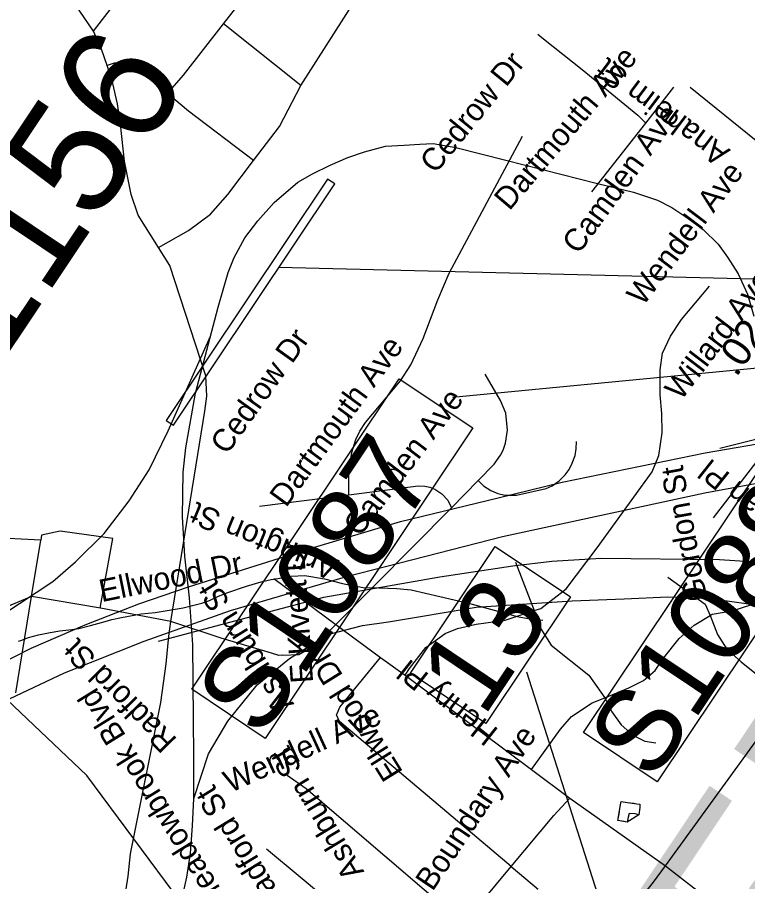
# Model space of a CAD drawing. Extents: x 1716282 to 1717158, y 799307 to 801078.
# Drawn here: x 1716763 to 1716807.8, y 800806.9 to 800859.9 of the extents above; entities that cross this region are included whole.
import ezdxf

# ---------------------------------------------------------------- set-up
doc = ezdxf.new("R2010")
doc.units = 0
for name, color, linetype in [('Exist Hydrographic Misc Water Feature', 7, 'Continuous'), ('Exist Road Non-System Structure Non-Sys Other Number Label', 7, 'Continuous'), ('Exist Road Non-System Type 51', 7, 'Continuous'), ('Exist Road Non-System Type 51 Label', 7, 'Continuous'), ('Exist Road Primary US Structure Ovrhead Sign CELL', 7, 'Continuous'), ('Exist Road Primary US Structure Standard Bridge Number Label', 7, 'Continuous'), ('Exist Road Secondary Mileage Hundredths English Label', 7, 'Continuous'), ('Exist Road Secondary Structure Standard Bridge Number Label', 7, 'Continuous'), ('Exist Road Secondary Type 51 Attributed', 7, 'Continuous'), ('Exist Road Secondary Type 51 Label', 7, 'Continuous'), ('Old_Level_1', 7, 'Continuous'), ('Prop Road Primary US Projected', 7, 'Continuous'), ('Prop Road Secondary Projected', 7, 'Continuous')]:
    doc.layers.add(name, color=color, linetype=linetype)

msp = doc.modelspace()

# ---------------------------------------------------------------- linework, layer by layer
at = {"layer": 'Exist Hydrographic Misc Water Feature'}
for points in [[(1716763.096, 800821.605), (1716763.227, 800821.662), (1716763.697, 800821.833), (1716764.31, 800822.011), (1716765.036, 800822.149), (1716765.624, 800822.237), (1716766.358, 800822.336), (1716766.784, 800822.394), (1716767.502, 800822.57), (1716768.415, 800822.825), (1716768.81, 800822.943), (1716769.416, 800823.057), (1716770.624, 800823.284), (1716771.487, 800823.363), (1716773.203, 800823.665), (1716774.341, 800823.942), (1716774.81, 800824.113), (1716775.327, 800824.357), (1716775.868, 800824.584), (1716777.088, 800824.98), (1716777.976, 800825.252), (1716778.597, 800825.391), (1716779, 800825.466), (1716779.831, 800825.601), (1716780.66, 800825.632), (1716781.865, 800825.441), (1716782.964, 800825.148), (1716784.24, 800824.909), (1716785.204, 800824.881), (1716786.3, 800824.838), (1716787.191, 800824.753), (1716790.706, 800823.934), (1716792.728, 800823.396), (1716793.699, 800823.12), (1716794.132, 800823.034), (1716794.518, 800822.982), (1716795.264, 800822.893)], [(1716779.752, 800768.606), (1716779.969, 800768.981), (1716779.06, 800773.412), (1716773.302, 800782.926), (1716773.169, 800783.886), (1716773.397, 800784.735), (1716773.329, 800786.33), (1716773.47, 800786.879), (1716774.435, 800788.237), (1716774.859, 800788.785), (1716775.418, 800789.507), (1716776.092, 800791.022), (1716776.356, 800794.292), (1716775.692, 800799.57), (1716773.061, 800805.606), (1716767.28, 800813.366), (1716762.4, 800818.012), (1716761.079, 800818.592)], [(1716800.07, 800811.775), (1716800.457, 800811.724), (1716800.842, 800811.67), (1716801.035, 800811.644), (1716801.228, 800811.618), (1716801.225, 800811.408), (1716801.164, 800810.959), (1716800.923, 800811.016), (1716800.562, 800811.054), (1716800.503, 800810.814), (1716800.435, 800810.508), (1716800.258, 800810.558), (1716799.873, 800810.612), (1716799.943, 800811.022), (1716800.004, 800811.471), (1716800.07, 800811.775)], [(1716800.07, 800811.775), (1716800.457, 800811.724), (1716801.035, 800811.644), (1716801.228, 800811.618), (1716801.225, 800811.408), (1716801.164, 800810.959), (1716800.435, 800810.508), (1716799.873, 800810.612), (1716800.004, 800811.471), (1716800.07, 800811.775)]]:
    msp.add_lwpolyline(points, dxfattribs=at)
at = {"layer": 'Exist Road Non-System Type 51'}
for p, q in [((1716767.686, 800859.012), (1716775.828, 800869.582)), ((1716775.679, 800859.473), (1716780.784, 800866.012)), ((1716780.415, 800855.698), (1716775.679, 800859.473)), ((1716801.589, 800853.374), (1716803.301, 800855.585)), ((1716798.269, 800849.175), (1716801.589, 800853.374)), ((1716805.745, 800829.179), (1716808.41, 800832.66)), ((1716789.67, 800829.785), (1716791.308, 800831.467)), ((1716777.878, 800829.887), (1716783.361, 800830.59)), ((1716782.569, 800822.64), (1716789.67, 800829.785)), ((1716763.89, 800824.349), (1716764.458, 800827.805)), ((1716793.597, 800826.457), (1716794.742, 800823.488)), ((1716778.766, 800825.447), (1716782.569, 800822.64)), ((1716762.934, 800818.435), (1716763.89, 800824.349)), ((1716768.126, 800823.638), (1716763.89, 800824.349)), ((1716772.447, 800822.815), (1716768.126, 800823.638)), ((1716782.569, 800822.64), (1716785.313, 800820.621)), ((1716785.313, 800820.621), (1716786.809, 800819.519)), ((1716786.809, 800819.519), (1716794.579, 800813.741)), ((1716802.788, 800807.834), (1716810.25, 800818.107)), ((1716794.579, 800813.741), (1716796.929, 800811.985)), ((1716796.929, 800811.985), (1716802.788, 800807.834)), ((1716790.405, 800804.316), (1716793.33, 800807.804)), ((1716793.33, 800807.804), (1716799.024, 800803.003)), ((1716802.788, 800807.834), (1716806.624, 800804.887))]:
    msp.add_line(p, q, dxfattribs=at)
for points in [[(1716780.415, 800855.698), (1716784.463, 800862.046), (1716784.606, 800862.629), (1716784.528, 800862.924), (1716784.476, 800863.148), (1716784.147, 800863.573), (1716780.784, 800866.012)], [(1716767.686, 800859.012), (1716766.863, 800860.237), (1716765.985, 800861.662), (1716765.21, 800862.818), (1716764.686, 800863.727)], [(1716772.238, 800855.2), (1716773.216, 800856.327), (1716775.679, 800859.473)], [(1716768.537, 800856.922), (1716768.174, 800857.907), (1716767.686, 800859.012)], [(1716794.956, 800858.838), (1716795.3, 800858.554), (1716797.685, 800856.67), (1716801.102, 800853.878), (1716801.589, 800853.374)], [(1716772.238, 800855.2), (1716771.5, 800855.803), (1716770.605, 800856.642), (1716770.173, 800856.918), (1716769.784, 800857.047), (1716769.377, 800857.097), (1716768.967, 800857.059), (1716768.537, 800856.922)], [(1716771.689, 800845.752), (1716770.443, 800847.742), (1716770.001, 800848.998), (1716769.598, 800851.045), (1716769.355, 800853.323), (1716769.159, 800854.569), (1716768.872, 800855.808), (1716768.537, 800856.922)], [(1716777.517, 800851.086), (1716779.109, 800853.179), (1716780.415, 800855.698)], [(1716804.298, 800855.582), (1716808.47, 800852.236), (1716816.668, 800845.833), (1716820.932, 800842.974)], [(1716777.517, 800851.086), (1716773.532, 800854.109), (1716772.238, 800855.2)], [(1716783.361, 800830.59), (1716783.368, 800832.016), (1716783.553, 800833.188), (1716783.784, 800833.985), (1716784.036, 800834.498), (1716784.386, 800835.021), (1716786.538, 800837.587), (1716787.169, 800838.556), (1716787.931, 800840.181), (1716788.816, 800842.538), (1716789.517, 800844.18), (1716794.023, 800852.575)], [(1716771.689, 800845.752), (1716773.523, 800846.789), (1716774.875, 800847.803), (1716775.944, 800849.01), (1716777.517, 800851.086)], [(1716772.447, 800822.815), (1716774.515, 800835.724), (1716774.641, 800836.638), (1716774.58, 800837.894), (1716772.375, 800844.644), (1716771.689, 800845.752)], [(1716794.742, 800823.488), (1716795.144, 800823.624), (1716796.706, 800824.829), (1716798.6, 800827.343), (1716801.966, 800831.991), (1716802.379, 800832.989), (1716802.591, 800834.381), (1716802.575, 800835.568), (1716802.475, 800836.711), (1716802.47, 800838.245), (1716802.603, 800839.277), (1716803.103, 800840.325), (1716803.786, 800841.347), (1716805.499, 800843.385)], [(1716791.308, 800831.467), (1716792.286, 800832.462), (1716792.677, 800833.02), (1716792.833, 800833.328), (1716792.981, 800833.761), (1716793.095, 800834.548), (1716792.994, 800835.602), (1716792.664, 800836.368), (1716791.727, 800837.979)], [(1716791.308, 800831.467), (1716791.633, 800831.146), (1716792.082, 800830.845), (1716792.497, 800830.671), (1716792.936, 800830.576), (1716793.655, 800830.575), (1716795.471, 800830.967), (1716795.843, 800831.147), (1716796.264, 800831.448), (1716796.636, 800831.812), (1716796.88, 800832.148), (1716797.072, 800832.519), (1716797.242, 800833.005), (1716797.312, 800833.412), (1716797.325, 800833.848)], [(1716783.361, 800830.59), (1716787.612, 800831.139), (1716788.026, 800831.128), (1716788.339, 800831.06), (1716788.636, 800830.944), (1716789.078, 800830.653), (1716789.43, 800830.262), (1716789.67, 800829.785)], [(1716805.53, 800823.194), (1716805.651, 800823.27), (1716806.881, 800823.467), (1716808.088, 800823.868), (1716808.782, 800824.164), (1716809.374, 800824.597), (1716810.094, 800825.215), (1716813.104, 800829.18)], [(1716764.458, 800827.805), (1716757.622, 800828.163), (1716757.592, 800828.124), (1716757.389, 800827.904), (1716754.952, 800824.667)], [(1716768.126, 800823.638), (1716768.118, 800823.763), (1716768.873, 800827.902), (1716765.652, 800828.358), (1716764.511, 800828.123), (1716764.458, 800827.805)], [(1716802.939, 800825.547), (1716805.234, 800823.887), (1716805.53, 800823.194)], [(1716763.89, 800824.349), (1716761.825, 800823.491), (1716759.904, 800823.11)], [(1716786.809, 800819.519), (1716787.091, 800819.939), (1716788.078, 800821.215), (1716789.269, 800822.08), (1716790.032, 800822.398), (1716791.176, 800822.655), (1716792.964, 800822.891), (1716794.742, 800823.488)], [(1716794.742, 800823.488), (1716795.137, 800822.362), (1716795.785, 800821.359), (1716798.08, 800819.526), (1716799.077, 800818.135)], [(1716769.303, 800803.915), (1716769.829, 800807.203), (1716769.97, 800808.57), (1716771.825, 800817.843), (1716772.142, 800820.217), (1716772.306, 800821.92), (1716772.447, 800822.815)], [(1716778.615, 800820.877), (1716775.536, 800821.806), (1716772.447, 800822.815)], [(1716799.077, 800818.135), (1716800.539, 800818.746), (1716801.449, 800819.195), (1716802.165, 800819.815), (1716802.671, 800820.571), (1716803.633, 800821.781), (1716804.562, 800822.596), (1716805.53, 800823.194)], [(1716805.53, 800823.194), (1716805.985, 800822.026), (1716806.553, 800821.114), (1716807.43, 800820.339), (1716810.25, 800818.107)], [(1716779.294, 800820.748), (1716780.3, 800820.796), (1716781.325, 800821.388), (1716782.569, 800822.64)], [(1716779.294, 800820.748), (1716779.076, 800820.739), (1716778.615, 800820.877)], [(1716793.33, 800807.804), (1716782.788, 800816.693), (1716782.608, 800817.088), (1716782.644, 800817.168), (1716782.817, 800817.557), (1716785.313, 800820.621)], [(1716794.579, 800813.741), (1716796.349, 800816.209), (1716797.036, 800817.001), (1716798.301, 800817.825), (1716799.077, 800818.135)], [(1716799.077, 800818.135), (1716799.495, 800817.288), (1716800.083, 800816.477), (1716800.798, 800815.849), (1716801.53, 800815.472), (1716802.194, 800815.381)], [(1716779.582, 800813.388), (1716780.752, 800812.576), (1716790.405, 800804.316)], [(1716793.33, 800807.804), (1716795.949, 800810.924), (1716796.929, 800811.985)], [(1716778.314, 800808.886), (1716780.383, 800807.155), (1716783.993, 800804.131)], [(1716799.024, 800803.003), (1716802.066, 800806.843), (1716802.788, 800807.834)]]:
    msp.add_lwpolyline(points, dxfattribs=at)
at = {"layer": 'Exist Road Primary US Structure Ovrhead Sign CELL'}
msp.add_line((1716832.181, 800840.62), (1716789.715, 800836.557), dxfattribs=at)
for points in [[(1716773.717, 800818.669), (1716786.46, 800837.708), (1716790.968, 800834.691), (1716778.225, 800815.652)], [(1716797.767, 800816.005), (1716810.51, 800835.044), (1716815.018, 800832.027), (1716802.275, 800812.988)]]:
    msp.add_lwpolyline(points, close=True, dxfattribs=at)
at = {"layer": 'Exist Road Primary US Structure Standard Bridge Number Label'}
for p, q in [((1716782.061, 800849.941), (1716772.16, 800835.147)), ((1716828.153, 800843.315), (1716779.047, 800844.528))]:
    msp.add_line(p, q, dxfattribs=at)
msp.add_lwpolyline([(1716772.16, 800835.147), (1716772.592, 800834.858), (1716782.494, 800849.651), (1716782.061, 800849.941)], dxfattribs=at)
at = {"layer": 'Exist Road Secondary Structure Standard Bridge Number Label'}
msp.add_line((1716806.647, 800781.09), (1716794.275, 800819.713), dxfattribs=at)
msp.add_lwpolyline([(1716787.156, 800819.656), (1716792.351, 800827.418), (1716796.958, 800824.335), (1716791.763, 800816.573)], close=True, dxfattribs=at)
at = {"layer": 'Exist Road Secondary Type 51 Attributed'}
msp.add_lwpolyline([(1716772.941, 800805.023), (1716773.43, 800807.144), (1716773.635, 800808.603), (1716773.776, 800810.281), (1716773.852, 800811.968), (1716773.852, 800814.564), (1716773.78, 800821.403), (1716773.583, 800824.28), (1716773.301, 800826.821), (1716773.151, 800829.245), (1716773.185, 800831.969), (1716773.369, 800833.477), (1716773.946, 800836.829), (1716775.334, 800842.102), (1716775.957, 800844.212), (1716776.319, 800845.145), (1716776.984, 800846.349), (1716777.787, 800847.391), (1716778.772, 800848.522), (1716780.238, 800849.769), (1716781.133, 800850.266), (1716782.213, 800850.806), (1716783.298, 800851.273), (1716784.322, 800851.623), (1716785.621, 800851.965), (1716786.753, 800852.031), (1716787.728, 800852.098), (1716788.529, 800852.141), (1716789.936, 800851.884), (1716792.991, 800851.102), (1716798.618, 800849.678), (1716800.838, 800849.14), (1716802.301, 800848.652), (1716803.19, 800848.198), (1716804.047, 800847.631), (1716804.413, 800847.379), (1716805.104, 800846.864), (1716806.028, 800845.964), (1716806.609, 800845.154), (1716807.259, 800844.132), (1716807.818, 800842.898), (1716808.212, 800841.546)], dxfattribs=at)
at = {"layer": 'Prop Road Primary US Projected'}
msp.add_line((1716806.138, 800833.439), (1716810.2, 800834.484), dxfattribs=at)
for points in [[(1716773.518, 800824.935), (1716780.996, 800827.293), (1716786.539, 800828.95), (1716792.522, 800830.4), (1716796.449, 800831.364), (1716805.234, 800833.158), (1716809.754, 800833.947), (1716814.34, 800834.669), (1716821.027, 800835.516), (1716827.101, 800836.241), (1716831.497, 800836.58), (1716834.544, 800836.759)], [(1716746.206, 800807.301), (1716748.75, 800809.402), (1716750.319, 800810.627), (1716751.951, 800811.796), (1716755.308, 800813.943), (1716758.37, 800815.777), (1716760.379, 800816.993), (1716762.19, 800817.914), (1716765.92, 800819.667), (1716770.8, 800821.603), (1716776.106, 800823.485), (1716783.304, 800825.604), (1716792.794, 800828.038), (1716805.216, 800830.706), (1716811.293, 800831.841)], [(1716771.68, 800821.618), (1716781.819, 800824.307), (1716788.943, 800825.566), (1716793.421, 800826.226), (1716795.819, 800826.513), (1716798.843, 800826.696), (1716806.109, 800826.625), (1716811.123, 800826.296), (1716812.227, 800826.25)], [(1716744.71, 800808.88), (1716746.097, 800810.124), (1716748.132, 800811.723), (1716749.565, 800812.804), (1716751.469, 800814.191), (1716755.317, 800816.627), (1716758.326, 800818.339), (1716760.515, 800819.49), (1716763.872, 800821.191), (1716767.176, 800822.616), (1716770.48, 800823.909), (1716773.518, 800824.935)]]:
    msp.add_lwpolyline(points, dxfattribs=at)
at = {"layer": 'Prop Road Secondary Projected'}
for points in [[(1716740.531, 800816.266), (1716745.274, 800817.651), (1716748.554, 800818.628), (1716756.509, 800821.035), (1716758.864, 800821.887), (1716760.784, 800822.535), (1716762.019, 800823.195), (1716763.151, 800823.924), (1716765.198, 800825.279), (1716766.594, 800826.476), (1716768.356, 800828.221), (1716769.89, 800830.217), (1716771.116, 800832.122), (1716772.274, 800834.519), (1716774.866, 800840.317)], [(1716773.852, 800811.968), (1716774.744, 800814.697), (1716775.939, 800816.71), (1716777.73, 800818.931), (1716779.729, 800820.556), (1716782.079, 800822.023), (1716784.2, 800822.58), (1716785.794, 800822.805), (1716791.173, 800823.688), (1716797.06, 800824.08), (1716800.265, 800824.215), (1716802.928, 800824.332), (1716804.942, 800824.276), (1716806.431, 800824.116), (1716808.165, 800823.867), (1716810.09, 800823.111), (1716811.507, 800822.39), (1716813.485, 800821.143), (1716814.831, 800819.862), (1716816.491, 800817.914)]]:
    msp.add_lwpolyline(points, dxfattribs=at)

# ---------------------------------------------------------------- texts
at = {"layer": 'Exist Road Non-System Structure Non-Sys Other Number Label'}
msp.add_text('J572', height=15.223, rotation=56.2051, dxfattribs=at).set_placement((1716807.118, 800787.797))
at = {"layer": 'Exist Road Non-System Type 51 Label'}
for s, rotation, p in [('Cedrow Dr', 50.8512, (1716788.678, 800850.224)), ('Dartmouth Ave', 49.8283, (1716793.215, 800847.962)), ('Anaheim St', 143.0271, (1716806.826, 800851.728)), ('Camden Ave', 53.9446, (1716797.463, 800845.278)), ('Wendell Ave', 52.8762, (1716801.409, 800842.107)), ('Willard Ave', 52.7017, (1716803.746, 800836.309)), ('Cedrow Dr', 54.4063, (1716775.881, 800832.991)), ('Dartmouth Ave', 53.749, (1716779.508, 800829.762)), ('Camden Ave', 52.7426, (1716784.024, 800827.959)), ('Morgan Pl', 141.5656, (1716812.128, 800827.639)), ('Gordon St', 100.33, (1716805.354, 800824.183)), ('Arlington St', 157.6641, (1716782.816, 800826.563)), ('Ellwood Dr', 11.4259, (1716768.191, 800824.004)), ('Ashburn St', 122.0781, (1716780.023, 800817.753)), ('Radford St', 134.5095, (1716772.88, 800815.604)), ('Ellwood Dr', 121.8391, (1716786.716, 800813.583)), ('Henry Pl', 141.6587, (1716792.61, 800816.177)), ('Meadowbrook Blvd', 121.7735, (1716776.079, 800805.536)), ('Wendell Ave', 24.6555, (1716776.086, 800812.29)), ('Boundary Ave', 56.2051, (1716788.499, 800806.226)), ('Ashburn St', 121.0525, (1716784.33, 800807.475)), ('Radford St', 121.3037, (1716779.64, 800805.358))]:
    msp.add_text(s, height=1.3775, rotation=rotation, dxfattribs=at).set_placement(p)
at = {"layer": 'Exist Road Primary US Structure Ovrhead Sign CELL'}
for s, p in [('S1087', (1716777.956, 800815.552)), ('S1088', (1716802.006, 800812.888))]:
    msp.add_text(s, height=5.075, rotation=56.2051, dxfattribs=at).set_placement(p)
at = {"layer": 'Exist Road Secondary Mileage Hundredths English Label'}
msp.add_text('.02', height=1.8125, rotation=55.3005, dxfattribs=at).set_placement((1716807.142, 800837.755))
at = {"layer": 'Exist Road Secondary Structure Standard Bridge Number Label'}
msp.add_text('13', height=5.075, rotation=56.2051, dxfattribs=at).set_placement((1716791.626, 800816.883))
at = {"layer": 'Exist Road Secondary Type 51 Label'}
msp.add_text('E Kivett Dr', height=1.3775, rotation=93.899, dxfattribs=at).set_placement((1716781.174, 800819.078))
at = {"layer": 'Old_Level_1'}
msp.add_text('1156', height=7.128, rotation=56.2051, dxfattribs=at).set_placement((1716761.812, 800838.284))

doc.saveas('drawing.dxf')
